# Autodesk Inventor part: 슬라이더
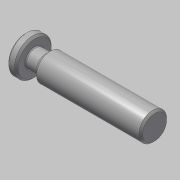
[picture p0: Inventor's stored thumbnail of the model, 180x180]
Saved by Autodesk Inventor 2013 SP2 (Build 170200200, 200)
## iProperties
Created: 2016-05
Part Number: 슬라이더
Document SubType Name: Modeling
Designer: mduedu
Density: 7.86 g/cm^3
Material: 강철, 연강
Author: mduedu
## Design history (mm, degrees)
sketch "스케치1"
  geometry: L1 (-7.5, 0)-(62.5, 0); L2 (62.5, 0)-(62.5, 7.5); L3 (62.5, 7.5)-(0, 7.5); L4 (-7.5, 0)-(-7.5, 10); L5 (-7.5, 10)-(-2.5, 10); L6 (-2.5, 10)-(-2.5, 5); L7 (-2.5, 5)-(3.5, 5); L8 (3.5, 5)-(6, 7.5); A1 r 7.5 centre (0, 0) between (0, 7.5) and (-7.5, 0); 1 further point
  constraints: 16 end point, 3 perpendicular, 2 horizontal, 2 parallel, 2 point on circle, 2 point on line, 2 tangent, 1 centre point, 1 coincident
  dimensions: "d0" = 15 diameter of A1; "d1" = 70 distance of L1.start L1.end; "d19" = 20 diameter of L5 L1; "d20" = 10 diameter of L7 L1; "d21" = 5 distance of L4.end L5.end; "d22" = 135 deg angle of L8 L7; "d23" = 6 distance of L6.end L7.end
revolve "회전1" stored, may be unused: angle "d4" = 90 deg
chamfer "모따기2" distance "d24" = 1; stored, may be unused: second distance "d25" = 2, angle "d26" = 45 deg
fillet "모깎기1" dims "d27" = 0.5
node "솔리드1"
